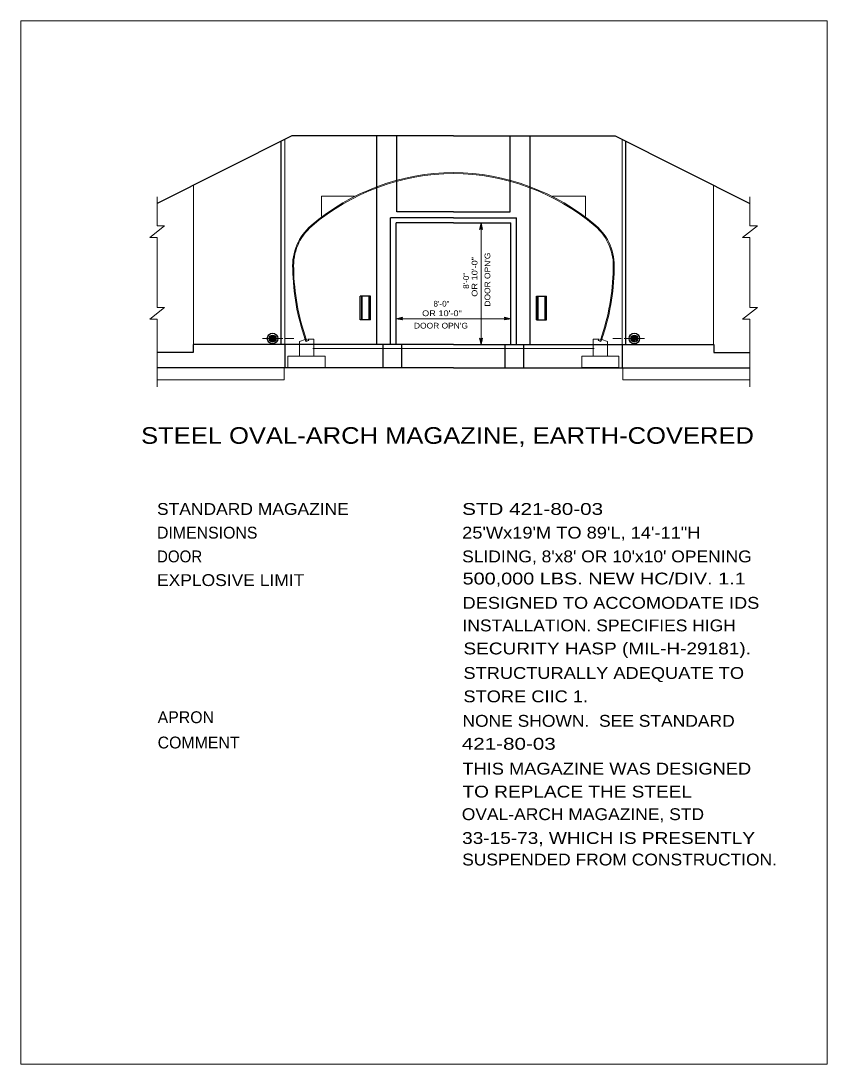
# Model space of a CAD drawing. Extents: x -22.3 to 19.7, y -11.8 to 18.2.
# Drawn here: x -0.3885 to -0.2999, y 0.3919 to 0.5065 of the extents above; entities that cross this region are included whole.
import ezdxf
from ezdxf.enums import TextEntityAlignment as Align

# ---------------------------------------------------------------- set-up
doc = ezdxf.new("R2010")
doc.units = 0
doc.header["$LTSCALE"] = 0.05
doc.linetypes.add('LONG_DASHED', pattern=[7.5, 6, -1.5])
doc.linetypes.add('MEDIUM_DASHED', pattern=[4.5, 3, -1.5])
doc.layers.add('1', color=7, linetype='Continuous', lineweight=13)

msp = doc.modelspace()

# ---------------------------------------------------------------- linework, layer by layer
at = {"layer": '1'}
for p, q in [((-0.38847, 0.50652), (-0.29993, 0.50652)), ((-0.38847, 0.39194), (-0.38847, 0.50652)), ((-0.29993, 0.39194), (-0.29993, 0.50652)), ((-0.37352, 0.48721), (-0.37352, 0.48401)), ((-0.30842, 0.48721), (-0.30842, 0.48401)), ((-0.37432, 0.48273), (-0.37268, 0.48401)), ((-0.37352, 0.48401), (-0.37268, 0.48401)), ((-0.33794, 0.48433), (-0.3381, 0.4836)), ((-0.33794, 0.48415), (-0.33803, 0.48368)), ((-0.33794, 0.48372), (-0.33803, 0.48368)), ((-0.33794, 0.48397), (-0.33799, 0.48374)), ((-0.33794, 0.48376), (-0.33799, 0.48374)), ((-0.33794, 0.47096), (-0.33794, 0.48433)), ((-0.33794, 0.48433), (-0.33778, 0.4836)), ((-0.33794, 0.48415), (-0.33783, 0.48368)), ((-0.33794, 0.48397), (-0.33789, 0.48374)), ((-0.33789, 0.48374), (-0.33794, 0.48376)), ((-0.33783, 0.48368), (-0.33794, 0.48372)), ((-0.30922, 0.48273), (-0.30757, 0.48401)), ((-0.30842, 0.48401), (-0.30757, 0.48401)), ((-0.37432, 0.48273), (-0.37352, 0.48273)), ((-0.37352, 0.48273), (-0.37352, 0.47504)), ((-0.30922, 0.48273), (-0.30842, 0.48273)), ((-0.30842, 0.48273), (-0.30842, 0.47504)), ((-0.37432, 0.47375), (-0.37268, 0.47504)), ((-0.37352, 0.47504), (-0.37268, 0.47504)), ((-0.30922, 0.47375), (-0.30757, 0.47504)), ((-0.30842, 0.47504), (-0.30757, 0.47504)), ((-0.37432, 0.47375), (-0.37352, 0.47375)), ((-0.37352, 0.47375), (-0.37352, 0.46632)), ((-0.34727, 0.47381), (-0.34656, 0.47398)), ((-0.33466, 0.47381), (-0.34727, 0.47381)), ((-0.34727, 0.47381), (-0.34656, 0.47367)), ((-0.34709, 0.47381), (-0.34662, 0.47392)), ((-0.34709, 0.47381), (-0.34662, 0.47372)), ((-0.34691, 0.47381), (-0.34669, 0.47386)), ((-0.34691, 0.47381), (-0.34669, 0.47376)), ((-0.34671, 0.47381), (-0.34669, 0.47386)), ((-0.34669, 0.47376), (-0.34671, 0.47381)), ((-0.34667, 0.47381), (-0.34662, 0.47392)), ((-0.34662, 0.47372), (-0.34667, 0.47381)), ((-0.33466, 0.47381), (-0.33537, 0.47398)), ((-0.33466, 0.47381), (-0.33537, 0.47367)), ((-0.33483, 0.47381), (-0.33531, 0.47392)), ((-0.33526, 0.47381), (-0.33531, 0.47392)), ((-0.33483, 0.47381), (-0.33531, 0.47372)), ((-0.33531, 0.47372), (-0.33526, 0.47381)), ((-0.33502, 0.47381), (-0.33525, 0.47386)), ((-0.33522, 0.47381), (-0.33525, 0.47386)), ((-0.33502, 0.47381), (-0.33525, 0.47376)), ((-0.33525, 0.47376), (-0.33522, 0.47381)), ((-0.30922, 0.47375), (-0.30842, 0.47375)), ((-0.30842, 0.47375), (-0.30842, 0.46632)), ((-0.35972, 0.47162), (-0.36193, 0.47162)), ((-0.35849, 0.47162), (-0.35941, 0.47162)), ((-0.33794, 0.47096), (-0.3381, 0.47168)), ((-0.33794, 0.47114), (-0.33803, 0.47161)), ((-0.33803, 0.47161), (-0.33794, 0.47156)), ((-0.33794, 0.47132), (-0.33799, 0.47155)), ((-0.33799, 0.47155), (-0.33794, 0.47153)), ((-0.33794, 0.47096), (-0.33778, 0.47168)), ((-0.33794, 0.47114), (-0.33783, 0.47161)), ((-0.33794, 0.47156), (-0.33783, 0.47161)), ((-0.33794, 0.47132), (-0.3379, 0.47155)), ((-0.33794, 0.47153), (-0.3379, 0.47155)), ((-0.32345, 0.47162), (-0.32253, 0.47162)), ((-0.32221, 0.47162), (-0.32, 0.47162)), ((-0.38847, 0.39194), (-0.29993, 0.39194))]:
    msp.add_line(p, q, dxfattribs=at)
at = {"layer": '1', "lineweight": 25}
for p, q in [((-0.34937, 0.47096), (-0.34937, 0.49388)), ((-0.3472, 0.48555), (-0.3472, 0.49388)), ((-0.33473, 0.48555), (-0.33473, 0.49388)), ((-0.33255, 0.47096), (-0.33255, 0.49388)), ((-0.3599, 0.47096), (-0.3599, 0.49328)), ((-0.32203, 0.47096), (-0.32203, 0.49328)), ((-0.34787, 0.47096), (-0.34787, 0.4849)), ((-0.34097, 0.4849), (-0.34787, 0.4849)), ((-0.34097, 0.48555), (-0.3472, 0.48555)), ((-0.34097, 0.48555), (-0.33473, 0.48555)), ((-0.34097, 0.4849), (-0.33405, 0.4849)), ((-0.33405, 0.47096), (-0.33405, 0.4849)), ((-0.34727, 0.47096), (-0.34727, 0.48433)), ((-0.34097, 0.48433), (-0.34727, 0.48433)), ((-0.34097, 0.48433), (-0.33466, 0.48433)), ((-0.33466, 0.47096), (-0.33466, 0.48433)), ((-0.3512, 0.47367), (-0.3512, 0.47629)), ((-0.35007, 0.47629), (-0.3512, 0.47629)), ((-0.35103, 0.47367), (-0.35103, 0.47629)), ((-0.35023, 0.47367), (-0.35023, 0.47629)), ((-0.35007, 0.47367), (-0.35007, 0.47629)), ((-0.33185, 0.47367), (-0.33185, 0.47629)), ((-0.33185, 0.47629), (-0.33073, 0.47629)), ((-0.3317, 0.47367), (-0.3317, 0.47629)), ((-0.3309, 0.47367), (-0.3309, 0.47629)), ((-0.33073, 0.47367), (-0.33073, 0.47629)), ((-0.35007, 0.47367), (-0.3512, 0.47367)), ((-0.33185, 0.47367), (-0.33073, 0.47367)), ((-0.361, 0.47142), (-0.361, 0.47184)), ((-0.3609, 0.47136), (-0.3609, 0.4719)), ((-0.36076, 0.47136), (-0.36076, 0.4719)), ((-0.36068, 0.47142), (-0.36068, 0.47184)), ((-0.35949, 0.47096), (-0.35949, 0.4684)), ((-0.34868, 0.4684), (-0.34868, 0.47096)), ((-0.34665, 0.4684), (-0.34665, 0.47096)), ((-0.33528, 0.4684), (-0.33528, 0.47096)), ((-0.33325, 0.4684), (-0.33325, 0.47096)), ((-0.32244, 0.47096), (-0.32244, 0.4684)), ((-0.32126, 0.47142), (-0.32126, 0.47184)), ((-0.32117, 0.47136), (-0.32117, 0.4719)), ((-0.32103, 0.47136), (-0.32103, 0.4719)), ((-0.32093, 0.47142), (-0.32093, 0.47184)), ((-0.36956, 0.47009), (-0.37352, 0.47009)), ((-0.31238, 0.47009), (-0.30842, 0.47009)), ((-0.34097, 0.4684), (-0.37352, 0.4684)), ((-0.34097, 0.4684), (-0.30842, 0.4684))]:
    msp.add_line(p, q, dxfattribs=at)
at = {"layer": '1', "linetype": 'LONG_DASHED'}
for p, q in [((-0.35949, 0.47096), (-0.35949, 0.49345)), ((-0.32244, 0.47096), (-0.32244, 0.49345)), ((-0.36953, 0.47096), (-0.36953, 0.4884)), ((-0.3124, 0.47096), (-0.3124, 0.4884)), ((-0.35956, 0.4684), (-0.35956, 0.46709)), ((-0.32236, 0.4684), (-0.32236, 0.46709)), ((-0.35956, 0.4671), (-0.37352, 0.4671)), ((-0.32236, 0.4671), (-0.30842, 0.4671))]:
    msp.add_line(p, q, dxfattribs=at)
at = {"layer": '1', "linetype": 'MEDIUM_DASHED'}
for p, q in [((-0.35099, 0.47367), (-0.35099, 0.47629)), ((-0.35027, 0.47367), (-0.35027, 0.47629)), ((-0.33167, 0.47367), (-0.33167, 0.47629)), ((-0.33094, 0.47367), (-0.33094, 0.47629)), ((-0.35725, 0.47153), (-0.35789, 0.4713)), ((-0.35789, 0.46969), (-0.35789, 0.4713)), ((-0.3573, 0.47166), (-0.35729, 0.47167)), ((-0.3573, 0.47166), (-0.35716, 0.47129)), ((-0.35729, 0.47167), (-0.35715, 0.47131)), ((-0.35685, 0.47142), (-0.35716, 0.47129)), ((-0.35715, 0.47159), (-0.35704, 0.47136)), ((-0.35695, 0.47156), (-0.35693, 0.47157)), ((-0.35693, 0.47157), (-0.35685, 0.47142)), ((-0.35693, 0.47157), (-0.35631, 0.47157)), ((-0.35631, 0.46969), (-0.35631, 0.47157)), ((-0.32561, 0.46969), (-0.32561, 0.47157)), ((-0.325, 0.47157), (-0.32561, 0.47157)), ((-0.325, 0.47157), (-0.32507, 0.47142)), ((-0.32507, 0.47142), (-0.32478, 0.47129)), ((-0.32498, 0.47156), (-0.325, 0.47157)), ((-0.32479, 0.47159), (-0.32489, 0.47136)), ((-0.32464, 0.47167), (-0.32479, 0.47131)), ((-0.32462, 0.47166), (-0.32478, 0.47129)), ((-0.32468, 0.47153), (-0.32405, 0.4713)), ((-0.32462, 0.47166), (-0.32464, 0.47167)), ((-0.32405, 0.46969), (-0.32405, 0.4713)), ((-0.34097, 0.47054), (-0.35642, 0.47054)), ((-0.34097, 0.47054), (-0.32552, 0.47054)), ((-0.35914, 0.46844), (-0.35914, 0.46969)), ((-0.35914, 0.46969), (-0.35505, 0.46969)), ((-0.35505, 0.46844), (-0.35505, 0.46969)), ((-0.32687, 0.46844), (-0.32687, 0.46969)), ((-0.32279, 0.46969), (-0.32687, 0.46969)), ((-0.32279, 0.46844), (-0.32279, 0.46969)), ((-0.35914, 0.46844), (-0.35505, 0.46844)), ((-0.32279, 0.46844), (-0.32687, 0.46844))]:
    msp.add_line(p, q, dxfattribs=at)
at = {"layer": '1', "lineweight": 25}
for points in [[(-0.34097, 0.49388), (-0.35871, 0.49388), (-0.37352, 0.48647)], [(-0.34097, 0.49388), (-0.32322, 0.49388), (-0.30842, 0.48647)], [(-0.34097, 0.47096), (-0.36956, 0.47096), (-0.36956, 0.47009)], [(-0.34097, 0.47096), (-0.31238, 0.47096), (-0.31238, 0.47009)]]:
    msp.add_lwpolyline(points, dxfattribs=at)
at = {"layer": '1', "linetype": 'MEDIUM_DASHED'}
for points in [[(-0.35185, 0.48727), (-0.35546, 0.48727), (-0.35546, 0.48507)], [(-0.33008, 0.48727), (-0.32647, 0.48727), (-0.32647, 0.48507)], [(-0.35695, 0.47156), (-0.35689, 0.47143), (-0.35715, 0.47131)], [(-0.32498, 0.47156), (-0.32504, 0.47143), (-0.32479, 0.47131)]]:
    msp.add_lwpolyline(points, dxfattribs=at)
at = {"layer": '1'}
for points in [[(-0.33778, 0.4836), (-0.33794, 0.48368), (-0.3381, 0.4836)], [(-0.34656, 0.47367), (-0.34662, 0.47381), (-0.34656, 0.47398)], [(-0.33537, 0.47367), (-0.33531, 0.47381), (-0.33537, 0.47398)], [(-0.3381, 0.47168), (-0.33794, 0.47161), (-0.33778, 0.47168)]]:
    msp.add_lwpolyline(points, dxfattribs=at)
at = {"layer": '1', "lineweight": 25}
for centre, radius in [((-0.36083, 0.47163), 0.000582), ((-0.3211, 0.47163), 0.000582), ((-0.36083, 0.47163), 0.000381), ((-0.3211, 0.47163), 0.000381)]:
    msp.add_circle(centre, radius, dxfattribs=at)
at = {"layer": '1', "linetype": 'MEDIUM_DASHED'}
for centre, radius, start, end in [((-0.34075, 0.46536), 0.024508, 90.50762, 130.28021), ((-0.34075, 0.46536), 0.024404, 90.50979, 130.28021), ((-0.34118, 0.46536), 0.024508, 49.71979, 89.49238), ((-0.34118, 0.46536), 0.024404, 49.71979, 89.49021), ((-0.35285, 0.47965), 0.005773, 130.38466, 183.72825), ((-0.35285, 0.47965), 0.00567, 130.38466, 183.72825), ((-0.32908, 0.47965), 0.00567, 356.27175, 49.61534), ((-0.32908, 0.47965), 0.005773, 356.27175, 49.61534), ((-0.33411, 0.47965), 0.024509, 180.86487, 199.33073), ((-0.33411, 0.47965), 0.024404, 180.86487, 199.33073), ((-0.34782, 0.47965), 0.024404, 340.66927, 359.13513), ((-0.34782, 0.47965), 0.024509, 340.66927, 359.13513)]:
    msp.add_arc(centre, radius, start, end, dxfattribs=at)
at = {"layer": '1', "lineweight": 25}
for centre, start, end in [((-0.36083, 0.47163), 131.18592, 230.19443), ((-0.36083, 0.47163), 75.96376, 104.03624), ((-0.36083, 0.47163), 257.24247, 285.06849), ((-0.36083, 0.47163), 306.8699, 53.97263), ((-0.3211, 0.47163), 126.02737, 233.1301), ((-0.3211, 0.47163), 254.93151, 282.75753), ((-0.3211, 0.47163), 75.96376, 104.03624), ((-0.3211, 0.47163), 309.80557, 48.81408)]:
    msp.add_arc(centre, 0.000272, start, end, dxfattribs=at)

# ---------------------------------------------------------------- texts
at = {"layer": '1'}
for s, width, p in [('OR 10\'-0"', 1.2, (-0.33833, 0.47622)), ("DOOR OPN'G", 1.1, (-0.33692, 0.47514)), ('8\'-0"', 1.05, (-0.33926, 0.47709))]:
    msp.add_text(s, height=0.0006284, rotation=90, dxfattribs=dict(at, width=width)).set_placement(p)
for s, height, width, p in [('8\'-0"', 0.0006284, 1.05, (-0.34316, 0.47514)), ('OR 10\'-0"', 0.0006284, 1.2, (-0.34441, 0.47409)), ("DOOR OPN'G", 0.0006284, 1.1, (-0.3453, 0.47273)), ('STANDARD MAGAZINE', 0.001302, 1.1, (-0.37352, 0.45226)), ('STD 421-80-03', 0.001302, 1.3, (-0.34001, 0.45226)), ('25\'Wx19\'M TO 89\'L, 14\'-11"H', 0.001302, 1.15, (-0.34001, 0.44966)), ('DOOR', 0.001302, 0.95, (-0.37352, 0.44705)), ("SLIDING, 8'x8' OR 10'x10' OPENING", 0.001302, 1.1, (-0.34001, 0.44705)), ('EXPLOSIVE LIMIT', 0.001302, 1.1, (-0.37352, 0.44445)), ('500,000 LBS. NEW HC/DIV. 1.1', 0.001302, 1.25, (-0.33996, 0.44462)), ('DESIGNED TO ACCOMODATE IDS', 0.001302, 1.15, (-0.33997, 0.44195)), ('INSTALLATION. SPECIFIES HIGH', 0.001302, 1.1, (-0.33997, 0.43947)), ('SECURITY HASP (MIL-H-29181).', 0.001302, 1.2, (-0.33987, 0.43694)), ('STRUCTURALLY ADEQUATE TO', 0.001302, 1.15, (-0.33987, 0.43425)), ('STORE CIIC 1.', 0.001302, 1.15, (-0.33987, 0.43168)), ('NONE SHOWN.  SEE STANDARD', 0.001302, 1.1, (-0.33998, 0.42899)), ('421-80-03', 0.001302, 1.3, (-0.34005, 0.42647)), ('THIS MAGAZINE WAS DESIGNED ', 0.001302, 1.15, (-0.33998, 0.42374)), ('TO REPLACE THE STEEL', 0.001302, 1.2, (-0.33997, 0.42122)), ('OVAL-ARCH MAGAZINE, STD', 0.001302, 1.1, (-0.34005, 0.41874)), ('33-15-73, WHICH IS PRESENTLY', 0.001302, 1.2, (-0.34001, 0.41612)), ('SUSPENDED FROM CONSTRUCTION.', 0.001302, 1.1, (-0.34001, 0.41376))]:
    msp.add_text(s, height=height, dxfattribs=dict(at, width=width)).set_placement(p)
at = {"layer": '1', "width": 1.15}
msp.add_text('STEEL OVAL-ARCH MAGAZINE, EARTH-COVERED', height=0.001823, dxfattribs=at).set_placement((-0.34162, 0.46007), align=Align.CENTER)
at = {"layer": '1'}
for s, p in [('DIMENSIONS', (-0.37352, 0.44966)), ('APRON', (-0.37345, 0.42939)), ('COMMENT', (-0.37345, 0.42661))]:
    msp.add_text(s, height=0.001302, dxfattribs=at).set_placement(p)

doc.saveas('drawing.dxf')
